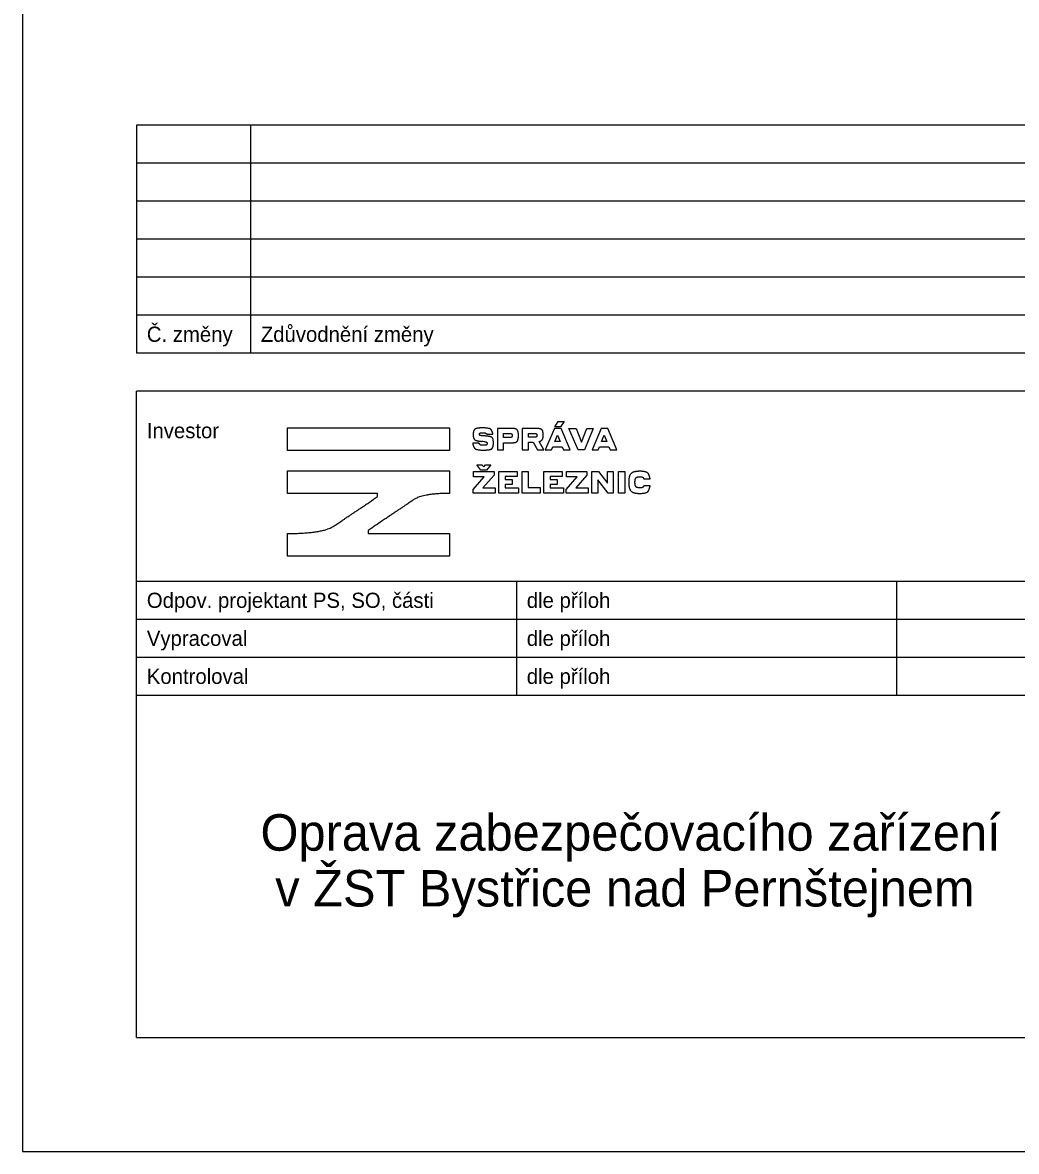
# Model space of a CAD drawing. Extents: x -790471 to -790261, y -983478 to -983181.
# Drawn here: x -790470.6 to -790339.8, y -983477.6 to -983329.1 of the extents above; entities that cross this region are included whole.
import ezdxf

# ---------------------------------------------------------------- set-up
doc = ezdxf.new("R2010")
doc.units = 0
for name, color, linetype in [('logo_sprava_zeleznic', 7, 'Continuous'), ('Ramečky', 7, 'Continuous'), ('Rámečky-tisk', 7, 'Continuous'), ('Text', 7, 'Continuous'), ('Text barevný', 7, 'Continuous')]:
    doc.layers.add(name, color=color, linetype=linetype)

msp = doc.modelspace()

# ---------------------------------------------------------------- linework, layer by layer
at = {"layer": 'logo_sprava_zeleznic'}
for p, q in [((-790400.56, -983382.26), (-790400.12, -983381.6)), ((-790400.12, -983381.6), (-790399.3, -983381.6)), ((-790399.3, -983381.6), (-790399.78, -983382.26)), ((-790409.51, -983383.23), (-790408.69, -983383.23)), ((-790399.78, -983382.26), (-790400.56, -983382.26)), ((-790398.7, -983382.48), (-790397.76, -983382.48)), ((-790397.49, -983385.29), (-790398.7, -983382.48)), ((-790397.76, -983382.48), (-790397.05, -983384.28)), ((-790397.05, -983384.28), (-790396.34, -983382.48)), ((-790395.49, -983382.48), (-790396.64, -983385.29)), ((-790396.34, -983382.48), (-790395.49, -983382.48)), ((-790410.51, -983384.45), (-790411.36, -983384.45)), ((-790409.76, -983383.48), (-790410.15, -983383.45)), ((-790396.64, -983385.29), (-790397.49, -983385.29)), ((-790410.29, -983387.96), (-790410.83, -983387.28)), ((-790410.83, -983387.28), (-790410.14, -983387.28)), ((-790410.14, -983387.28), (-790409.91, -983387.56)), ((-790409.91, -983387.56), (-790409.68, -983387.28)), ((-790409.68, -983387.28), (-790408.97, -983387.28)), ((-790408.97, -983387.28), (-790409.53, -983387.96)), ((-790411.3, -983390.53), (-790409.84, -983388.86)), ((-790411.26, -983388.17), (-790408.55, -983388.17)), ((-790411.26, -983388.86), (-790411.26, -983388.17)), ((-790409.84, -983388.86), (-790411.26, -983388.86)), ((-790409.53, -983387.96), (-790410.29, -983387.96)), ((-790408.55, -983388.63), (-790410.02, -983390.29)), ((-790408.55, -983388.17), (-790408.55, -983388.63)), ((-790407.92, -983388.17), (-790405.49, -983388.17)), ((-790407.92, -983390.99), (-790407.92, -983388.17)), ((-790405.49, -983388.83), (-790407.1, -983388.83)), ((-790407.1, -983388.83), (-790407.1, -983389.2)), ((-790407.1, -983389.2), (-790406.14, -983389.2)), ((-790406.14, -983389.2), (-790406.14, -983389.87)), ((-790405.49, -983388.17), (-790405.49, -983388.83)), ((-790404.86, -983388.17), (-790404.05, -983388.17)), ((-790404.86, -983390.99), (-790404.86, -983388.17)), ((-790404.05, -983388.17), (-790404.05, -983390.28)), ((-790401.99, -983388.17), (-790399.57, -983388.17)), ((-790401.99, -983390.99), (-790401.99, -983388.17)), ((-790399.57, -983388.83), (-790401.18, -983388.83)), ((-790401.18, -983388.83), (-790401.18, -983389.2)), ((-790401.18, -983389.2), (-790400.22, -983389.2)), ((-790400.22, -983389.2), (-790400.22, -983389.87)), ((-790399.57, -983388.17), (-790399.57, -983388.83)), ((-790399.07, -983390.53), (-790397.61, -983388.86)), ((-790399.03, -983388.17), (-790396.33, -983388.17)), ((-790399.03, -983388.86), (-790399.03, -983388.17)), ((-790397.61, -983388.86), (-790399.03, -983388.86)), ((-790396.33, -983388.63), (-790397.8, -983390.29)), ((-790396.33, -983388.17), (-790396.33, -983388.63)), ((-790395.69, -983388.17), (-790394.78, -983388.17)), ((-790395.69, -983390.99), (-790395.69, -983388.17)), ((-790393.53, -983390.99), (-790394.89, -983389.26)), ((-790394.89, -983389.26), (-790394.89, -983390.99)), ((-790394.78, -983388.17), (-790393.63, -983389.68)), ((-790393.63, -983389.68), (-790393.63, -983388.17)), ((-790393.63, -983388.17), (-790392.85, -983388.17)), ((-790392.85, -983388.17), (-790392.85, -983390.99)), ((-790388.84, -983389.12), (-790388.01, -983389.12)), ((-790411.3, -983390.99), (-790411.3, -983390.53)), ((-790410.02, -983390.29), (-790408.39, -983390.29)), ((-790408.39, -983390.29), (-790408.39, -983390.99)), ((-790406.14, -983389.87), (-790407.1, -983389.87)), ((-790407.1, -983389.87), (-790407.1, -983390.3)), ((-790407.1, -983390.3), (-790405.34, -983390.3)), ((-790405.34, -983390.3), (-790405.34, -983390.99)), ((-790404.05, -983390.28), (-790402.47, -983390.28)), ((-790402.47, -983390.28), (-790402.47, -983390.99)), ((-790400.22, -983389.87), (-790401.18, -983389.87)), ((-790401.18, -983389.87), (-790401.18, -983390.3)), ((-790401.18, -983390.3), (-790399.41, -983390.3)), ((-790399.41, -983390.3), (-790399.41, -983390.99)), ((-790399.07, -983390.99), (-790399.07, -983390.53)), ((-790397.8, -983390.29), (-790396.16, -983390.29)), ((-790396.16, -983390.29), (-790396.16, -983390.99)), ((-790388.01, -983390.05), (-790388.83, -983390.05)), ((-790408.39, -983390.99), (-790411.3, -983390.99)), ((-790405.34, -983390.99), (-790407.92, -983390.99)), ((-790402.47, -983390.99), (-790404.86, -983390.99)), ((-790399.41, -983390.99), (-790401.99, -983390.99)), ((-790396.16, -983390.99), (-790399.07, -983390.99)), ((-790394.89, -983390.99), (-790395.69, -983390.99)), ((-790392.85, -983390.99), (-790393.53, -983390.99))]:
    msp.add_line(p, q, dxfattribs=at)
for points in [[(-790435.73, -983382.4), (-790414.41, -983382.4), (-790414.41, -983385.38), (-790435.73, -983385.38)], [(-790401.8, -983385.29), (-790400.98, -983385.29), (-790400.82, -983384.89), (-790399.57, -983384.89), (-790399.41, -983385.29), (-790398.53, -983385.29), (-790399.73, -983382.48), (-790400.6, -983382.48)], [(-790395.65, -983385.29), (-790394.83, -983385.29), (-790394.66, -983384.89), (-790393.42, -983384.89), (-790393.26, -983385.29), (-790392.38, -983385.29), (-790393.57, -983382.48), (-790394.45, -983382.48)], [(-790400.19, -983383.39), (-790399.85, -983384.23), (-790400.54, -983384.23)], [(-790394.04, -983383.39), (-790393.7, -983384.23), (-790394.39, -983384.23)], [(-790392.16, -983388.17), (-790391.35, -983388.17), (-790391.35, -983390.99), (-790392.16, -983390.99)]]:
    msp.add_lwpolyline(points, close=True, dxfattribs=at)
for points in [[(-790406.38, -983382.48), (-790408.11, -983382.48), (-790408.11, -983385.29), (-790407.3, -983385.29), (-790407.3, -983384.39), (-790406.38, -983384.39)], [(-790406.48, -983383.69), (-790407.3, -983383.69), (-790407.3, -983383.17), (-790406.48, -983383.17)], [(-790403.12, -983382.48), (-790404.84, -983382.48), (-790404.84, -983385.29), (-790404.03, -983385.29), (-790404.03, -983384.31), (-790403.39, -983384.31), (-790402.84, -983385.29), (-790401.98, -983385.29), (-790402.59, -983384.22)], [(-790403.22, -983383.64), (-790404.03, -983383.64), (-790404.03, -983383.16), (-790403.22, -983383.16)], [(-790423.87, -983391.46), (-790423.87, -983391.04), (-790435.73, -983391.04), (-790435.73, -983388.07), (-790414.41, -983388.07), (-790414.41, -983391.04)], [(-790425.1, -983395.91), (-790425.1, -983396.32), (-790414.41, -983396.32), (-790414.41, -983399.3), (-790435.73, -983399.3), (-790435.73, -983396.32), (-790435.71, -983396.32)]]:
    msp.add_lwpolyline(points, dxfattribs=at)
for centre, radius, start, end in [((-790411.9, -983405.14), 21.01, 84.2634, 85.3384), ((-790461.18, -983338.6), 64.69, 304.0901, 305.2133), ((-790124.63, -983832.54), 530.02, 124.292, 124.5333)]:
    msp.add_arc(centre, radius, start, end, dxfattribs=at)
for points in [[(-790410.05, -983382.42), (-790410.77, -983382.42), (-790411.29, -983382.71), (-790411.29, -983383.28)], [(-790411.29, -983383.28), (-790411.29, -983383.83), (-790410.87, -983384.14), (-790410.19, -983384.2)], [(-790410.46, -983383.24), (-790410.46, -983383.12), (-790410.3, -983383.06), (-790410.05, -983383.06)], [(-790410.15, -983383.45), (-790410.35, -983383.43), (-790410.46, -983383.36), (-790410.46, -983383.24)], [(-790408.69, -983383.23), (-790408.77, -983382.87), (-790409.09, -983382.42), (-790410.05, -983382.42)], [(-790410.05, -983383.06), (-790409.73, -983383.06), (-790409.55, -983383.17), (-790409.51, -983383.23)], [(-790406.48, -983383.17), (-790406.27, -983383.17), (-790406.17, -983383.26), (-790406.17, -983383.43)], [(-790405.34, -983383.43), (-790405.34, -983382.8), (-790405.73, -983382.48), (-790406.38, -983382.48)], [(-790403.22, -983383.16), (-790403.02, -983383.16), (-790402.91, -983383.23), (-790402.91, -983383.4)], [(-790402.08, -983383.4), (-790402.08, -983382.79), (-790402.49, -983382.48), (-790403.12, -983382.48)], [(-790411.36, -983384.45), (-790411.29, -983384.84), (-790410.93, -983385.34), (-790409.92, -983385.34)], [(-790409.92, -983384.71), (-790410.28, -983384.71), (-790410.46, -983384.57), (-790410.51, -983384.45)], [(-790409.92, -983385.34), (-790409.08, -983385.34), (-790408.63, -983385), (-790408.63, -983384.4)], [(-790409.47, -983384.46), (-790409.47, -983384.61), (-790409.6, -983384.71), (-790409.92, -983384.71)], [(-790409.8, -983384.23), (-790409.6, -983384.26), (-790409.47, -983384.31), (-790409.47, -983384.46)], [(-790408.63, -983384.4), (-790408.63, -983383.79), (-790409.03, -983383.53), (-790409.76, -983383.48)], [(-790406.17, -983383.43), (-790406.17, -983383.59), (-790406.27, -983383.69), (-790406.48, -983383.69)], [(-790406.38, -983384.39), (-790405.73, -983384.39), (-790405.34, -983384.06), (-790405.34, -983383.43)], [(-790402.91, -983383.4), (-790402.91, -983383.55), (-790403.02, -983383.64), (-790403.22, -983383.64)], [(-790402.59, -983384.22), (-790402.27, -983384.08), (-790402.08, -983383.8), (-790402.08, -983383.4)], [(-790389.36, -983388.13), (-790390.22, -983388.13), (-790390.82, -983388.73), (-790390.82, -983389.58)], [(-790390, -983389.58), (-790390, -983389.18), (-790389.76, -983388.85), (-790389.36, -983388.85)], [(-790388.01, -983389.12), (-790388.06, -983388.8), (-790388.4, -983388.13), (-790389.36, -983388.13)], [(-790389.36, -983388.85), (-790389.02, -983388.85), (-790388.88, -983389.05), (-790388.84, -983389.12)], [(-790390.82, -983389.58), (-790390.82, -983390.43), (-790390.22, -983391.04), (-790389.36, -983391.04)], [(-790389.36, -983390.31), (-790389.76, -983390.31), (-790390, -983389.99), (-790390, -983389.58)], [(-790389.36, -983391.04), (-790388.37, -983391.04), (-790388.05, -983390.31), (-790388.01, -983390.05)], [(-790388.83, -983390.05), (-790388.87, -983390.12), (-790389.02, -983390.31), (-790389.36, -983390.31)], [(-790435.71, -983396.32), (-790431.06, -983396.31), (-790428.08, -983394.3), (-790424.92, -983392.18)], [(-790414.41, -983391.04), (-790417.9, -983391.04), (-790420.38, -983392.71), (-790423.25, -983394.65)]]:
    msp.add_open_spline(points, degree=2, dxfattribs=at)
at = {"layer": 'Ramečky'}
for p, q in [((-790275.59, -983342.6), (-790455.59, -983342.6)), ((-790455.59, -983342.6), (-790455.59, -983372.6)), ((-790440.59, -983342.6), (-790440.59, -983372.6)), ((-790305.59, -983347.6), (-790455.59, -983347.6)), ((-790305.59, -983352.6), (-790455.59, -983352.6)), ((-790305.59, -983357.6), (-790455.59, -983357.6)), ((-790305.59, -983362.6), (-790455.59, -983362.6)), ((-790305.59, -983367.6), (-790455.59, -983367.6)), ((-790275.59, -983372.6), (-790455.59, -983372.6)), ((-790275.59, -983377.6), (-790455.59, -983377.6)), ((-790455.59, -983462.6), (-790455.59, -983377.6)), ((-790455.59, -983402.6), (-790325.59, -983402.6)), ((-790455.59, -983407.6), (-790325.59, -983407.6)), ((-790455.59, -983412.6), (-790325.59, -983412.6)), ((-790455.59, -983417.6), (-790325.59, -983417.6)), ((-790455.59, -983462.6), (-790275.59, -983462.6))]:
    msp.add_line(p, q, dxfattribs=at)
for points in [[(-790405.59, -983402.6), (-790405.59, -983417.6)], [(-790355.59, -983402.6), (-790355.59, -983417.6)]]:
    msp.add_lwpolyline(points, dxfattribs=at)
at = {"layer": 'Rámečky-tisk'}
msp.add_line((-790470.59, -983180.6), (-790470.59, -983477.6), dxfattribs=at)
msp.add_lwpolyline([(-790470.59, -983477.6), (-790260.59, -983477.6), (-790260.59, -983180.6)], dxfattribs=at)

# ---------------------------------------------------------------- texts
at = {"layer": 'Text'}
for s, p in [('Č. změny', (-790454.24, -983371.1)), ('Zdůvodnění změny', (-790439.24, -983371.1)), ('Investor', (-790454.24, -983383.78)), ('Odpov. projektant PS, SO, části', (-790454.24, -983406.1)), ('dle příloh', (-790404.24, -983406.1)), ('Vypracoval', (-790454.24, -983411.1)), ('dle příloh', (-790404.24, -983411.1)), ('Kontroloval', (-790454.24, -983416.1)), ('dle příloh', (-790404.24, -983416.1))]:
    msp.add_text(s, height=2, dxfattribs=at).set_placement(p)
at = {"layer": 'Text barevný'}
for s, p in [('Oprava zabezpečovacího zařízení', (-790439.28, -983438.04)), ('v ŽST Bystřice nad Pernštejnem', (-790437.34, -983445.38))]:
    msp.add_text(s, height=4.8, dxfattribs=at).set_placement(p)

doc.saveas('drawing.dxf')
